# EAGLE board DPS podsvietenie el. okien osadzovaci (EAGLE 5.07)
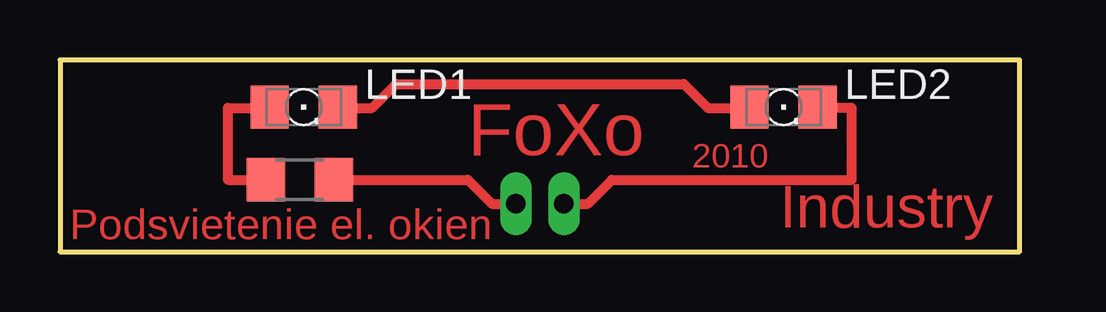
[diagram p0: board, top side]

Size 40 x 8 mm. Coordinates in mm from the lower left corner, seen from the top.
Outline: 0,0 40,0 40,8 0,8 0,0
Copper layers (1*16): Top 0.035mm / dielectric 1.5mm / Bottom 0.035mm
Design rules "default": minimum track width 10mil, minimum drill 24mil, track to track 8mil, track to pad 8mil, pad to pad 8mil, via to via 8mil, smd to smd 8mil, copper to edge 40mil, drill to drill 8mil, minimum pad ring 10mil, minimum via ring 8mil, stop-mask expansion 4mil, vias tented up to drill 0mil, thermal gap 10mil

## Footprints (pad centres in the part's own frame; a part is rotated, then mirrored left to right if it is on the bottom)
PAD_1--- = drill 0.813 pad 1.27 long: 1 0,0
R1206 = smd 1.6 x 1.803: 1 -1.422,0; 2 1.422,0
1206 = smd 1.6 x 1.803: A -1.422,0; C 1.422,0

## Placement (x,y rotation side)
+  [PAD_1---]  19,2 90 top
-  [PAD_1---]  21,2 90 top
E$1  R1  [R1206]  10,3 0 top
LED1  [1206]  10.16,6.03 0 top
LED2  [1206]  30.16,6.03 0 top

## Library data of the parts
+ - = #PaJa_21
E$1 = rcl
LED1 LED2 = led

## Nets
S$1: +.1
S$2: E$1.1
S$4: -.1

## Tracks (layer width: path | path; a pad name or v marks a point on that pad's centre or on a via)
S$1
  Top 0.406: +.1 18,2 17,3 12,3
S$2
  Top 0.406: E$1.1 7,3 7,6 8.41,6
S$3
  Top 0.406: 28.41,6 27,6 26,7 14,7 13,6 11.59,6
S$4
  Top 0.406: -.1 22,2 23,3 33,3 33,6 31.59,6

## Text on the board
Top: FoXo | 2010 | Industry | Podsvietenie el. okien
